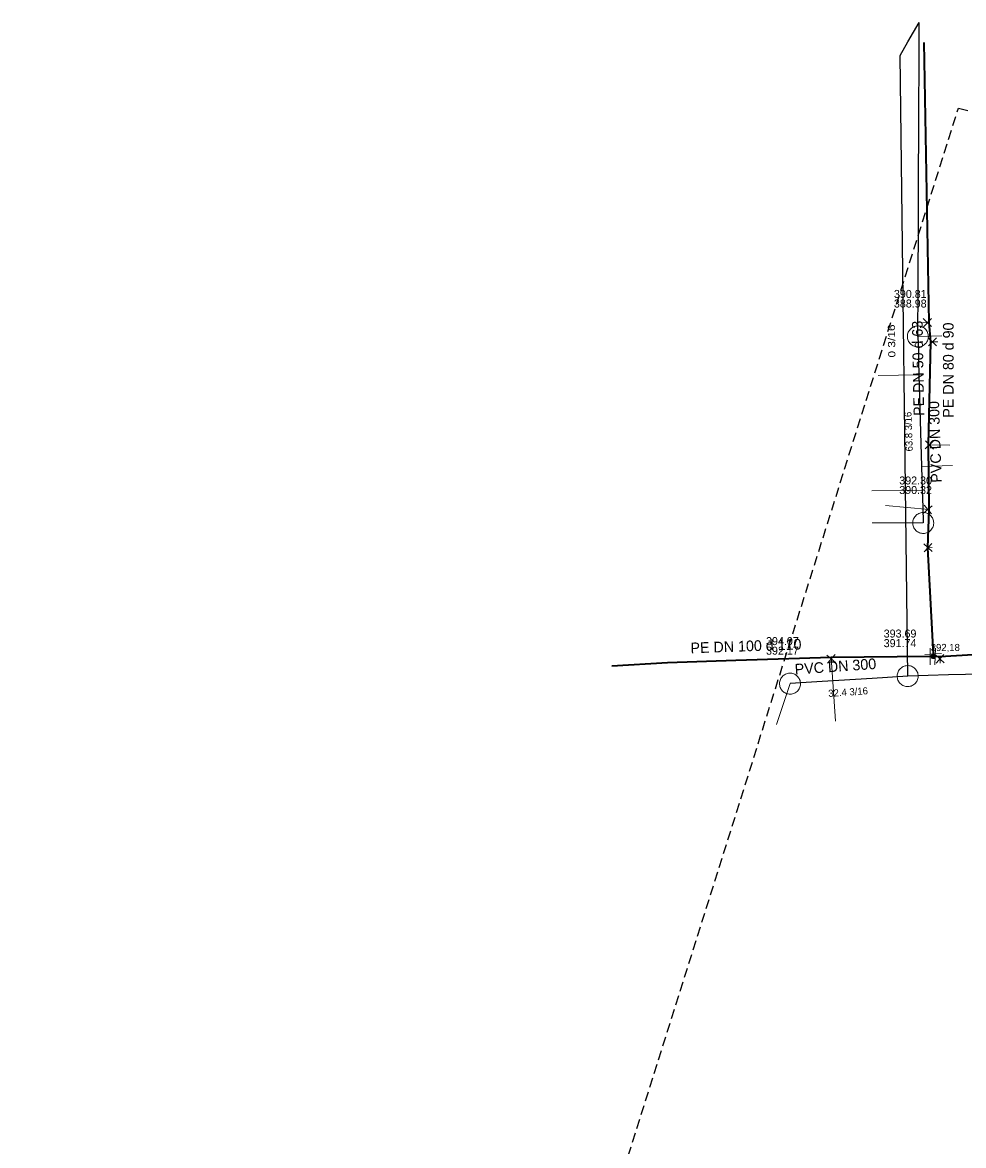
# Model space of a CAD drawing. Extents: x -772952 to -772403, y -1033777 to -1033210.
# Drawn here: x -772951.7 to -772845.8, y -1033366.6 to -1033240.3 of the extents above; entities that cross this region are included whole.
import ezdxf

# ---------------------------------------------------------------- set-up
doc = ezdxf.new("R2010")
doc.units = 0
doc.header["$LTSCALE"] = 0.36
doc.linetypes.add('MEDIUM_DASHED', pattern=[4.5, 3, -1.5])
for name, color, linetype, lineweight in [('15', 7, 'Continuous', 13), ('16', 7, 'Continuous', 35), ('2', 7, 'Continuous', 25), ('20', 7, 'Continuous', 13), ('4', 7, 'Continuous', 13), ('57', 7, 'Continuous', 13), ('59', 7, 'Continuous', 13), ('62', 7, 'MEDIUM_DASHED', 25)]:
    doc.layers.add(name, color=color, linetype=linetype, lineweight=lineweight)
for name, color, linetype in [('17', 7, 'Continuous'), ('3', 7, 'Continuous'), ('6', 7, 'Continuous')]:
    doc.layers.add(name, color=color, linetype=linetype)

msp = doc.modelspace()

# ---------------------------------------------------------------- linework, layer by layer
at = {"layer": '15'}
for p, q in [((-772850.349, -1033273.617), (-772849.404, -1033274.512)), ((-772849.434, -1033273.596), (-772850.323, -1033274.532)), ((-772848.839, -1033276.682), (-772849.78, -1033275.783)), ((-772849.754, -1033276.699), (-772848.86, -1033275.767)), ((-772850.115, -1033288.268), (-772849.181, -1033287.376)), ((-772849.2, -1033288.291), (-772850.101, -1033287.352)), ((-772849.326, -1033294.682), (-772850.32, -1033295.506)), ((-772850.237, -1033294.594), (-772849.404, -1033295.595)), ((-772849.334, -1033299.819), (-772850.298, -1033298.944)), ((-772850.248, -1033299.859), (-772849.378, -1033298.905)), ((-772849.568, -1033312.563), (-772849.585, -1033310.701)), ((-772849.045, -1033312.567), (-772848.97, -1033310.707)), ((-772861.183, -1033311.468), (-772860.213, -1033312.318)), ((-772861.126, -1033312.381), (-772860.27, -1033311.4)), ((-772848.304, -1033311.3), (-772850.164, -1033311.399)), ((-772848.932, -1033311.463), (-772847.984, -1033312.339)), ((-772848.898, -1033312.377), (-772848.017, -1033311.419))]:
    msp.add_line(p, q, dxfattribs=at)
for points in [[(-772849.449, -1033311.619), (-772849.445, -1033311.671), (-772849.43, -1033311.722), (-772849.403, -1033311.767), (-772849.368, -1033311.805), (-772849.324, -1033311.834), (-772849.275, -1033311.853), (-772849.222, -1033311.859), (-772849.169, -1033311.854), (-772849.12, -1033311.837), (-772849.076, -1033311.81), (-772849.038, -1033311.772), (-772849.01, -1033311.728), (-772848.992, -1033311.678), (-772848.987, -1033311.626), (-772848.993, -1033311.574), (-772849.011, -1033311.524), (-772849.04, -1033311.48), (-772849.078, -1033311.444), (-772849.123, -1033311.417), (-772849.173, -1033311.401), (-772849.226, -1033311.397), (-772849.278, -1033311.404), (-772849.326, -1033311.424), (-772849.371, -1033311.453), (-772849.406, -1033311.492), (-772849.432, -1033311.537), (-772849.446, -1033311.588)], [(-772849.419, -1033311.62), (-772849.415, -1033311.669), (-772849.4, -1033311.716), (-772849.374, -1033311.757), (-772849.338, -1033311.79), (-772849.295, -1033311.814), (-772849.247, -1033311.827), (-772849.198, -1033311.829), (-772849.151, -1033311.818), (-772849.107, -1033311.796), (-772849.07, -1033311.764), (-772849.041, -1033311.724), (-772849.023, -1033311.678), (-772849.017, -1033311.629), (-772849.022, -1033311.581), (-772849.04, -1033311.535), (-772849.068, -1033311.494), (-772849.105, -1033311.461), (-772849.148, -1033311.44), (-772849.195, -1033311.428), (-772849.244, -1033311.428), (-772849.292, -1033311.441), (-772849.336, -1033311.464), (-772849.371, -1033311.497), (-772849.399, -1033311.538), (-772849.415, -1033311.584)], [(-772849.389, -1033311.621), (-772849.385, -1033311.666), (-772849.37, -1033311.709), (-772849.343, -1033311.745), (-772849.308, -1033311.774), (-772849.267, -1033311.792), (-772849.222, -1033311.799), (-772849.177, -1033311.795), (-772849.135, -1033311.777), (-772849.099, -1033311.751), (-772849.071, -1033311.715), (-772849.053, -1033311.674), (-772849.047, -1033311.629), (-772849.053, -1033311.584), (-772849.07, -1033311.542), (-772849.098, -1033311.507), (-772849.133, -1033311.479), (-772849.176, -1033311.462), (-772849.221, -1033311.457), (-772849.266, -1033311.463), (-772849.307, -1033311.481), (-772849.342, -1033311.509), (-772849.369, -1033311.546), (-772849.385, -1033311.588)], [(-772849.359, -1033311.622), (-772849.356, -1033311.664), (-772849.34, -1033311.701), (-772849.314, -1033311.733), (-772849.28, -1033311.756), (-772849.24, -1033311.768), (-772849.199, -1033311.768), (-772849.16, -1033311.756), (-772849.125, -1033311.734), (-772849.098, -1033311.703), (-772849.082, -1033311.665), (-772849.077, -1033311.625), (-772849.084, -1033311.584), (-772849.102, -1033311.548), (-772849.13, -1033311.517), (-772849.166, -1033311.497), (-772849.206, -1033311.487), (-772849.247, -1033311.49), (-772849.286, -1033311.503), (-772849.319, -1033311.528), (-772849.343, -1033311.561), (-772849.357, -1033311.599)], [(-772849.329, -1033311.624), (-772849.326, -1033311.66), (-772849.309, -1033311.692), (-772849.284, -1033311.718), (-772849.251, -1033311.735), (-772849.215, -1033311.739), (-772849.18, -1033311.733), (-772849.148, -1033311.714), (-772849.124, -1033311.687), (-772849.109, -1033311.653), (-772849.108, -1033311.616), (-772849.118, -1033311.581), (-772849.137, -1033311.551), (-772849.166, -1033311.529), (-772849.201, -1033311.518), (-772849.238, -1033311.518), (-772849.273, -1033311.531), (-772849.301, -1033311.553), (-772849.321, -1033311.584), (-772849.329, -1033311.619)], [(-772849.299, -1033311.625), (-772849.296, -1033311.656), (-772849.28, -1033311.683), (-772849.254, -1033311.701), (-772849.225, -1033311.709), (-772849.194, -1033311.706), (-772849.166, -1033311.69), (-772849.147, -1033311.667), (-772849.138, -1033311.636), (-772849.141, -1033311.606), (-772849.154, -1033311.578), (-772849.178, -1033311.558), (-772849.207, -1033311.547), (-772849.238, -1033311.549), (-772849.267, -1033311.562), (-772849.288, -1033311.585), (-772849.299, -1033311.614)], [(-772849.269, -1033311.626), (-772849.265, -1033311.65), (-772849.249, -1033311.669), (-772849.227, -1033311.679), (-772849.202, -1033311.677), (-772849.181, -1033311.664), (-772849.169, -1033311.642), (-772849.168, -1033311.617), (-772849.179, -1033311.596), (-772849.199, -1033311.581), (-772849.223, -1033311.577), (-772849.247, -1033311.585), (-772849.263, -1033311.602)], [(-772849.239, -1033311.627), (-772849.235, -1033311.642), (-772849.22, -1033311.649), (-772849.205, -1033311.646), (-772849.198, -1033311.632), (-772849.201, -1033311.617), (-772849.214, -1033311.607), (-772849.229, -1033311.61), (-772849.239, -1033311.621)]]:
    msp.add_lwpolyline(points, close=True, dxfattribs=at)
at = {"layer": '16'}
for p, q in [((-772849.219, -1033311.629), (-772849.577, -1033311.633)), ((-772849.234, -1033311.35), (-772849.219, -1033311.629)), ((-772849.008, -1033311.638), (-772849.219, -1033311.629))]:
    msp.add_line(p, q, dxfattribs=at)
for points in [[(-772850.285, -1033242.579), (-772849.71, -1033274.059), (-772849.539, -1033276.239), (-772849.809, -1033287.82), (-772849.728, -1033295.103), (-772849.87, -1033299.386), (-772849.234, -1033311.35)], [(-772849.577, -1033311.633), (-772860.71, -1033311.739), (-772871.449, -1033312.079), (-772879.129, -1033312.329), (-772885.375, -1033312.733)], [(-772816.318, -1033310.962), (-772833.089, -1033311.01), (-772839.089, -1033311.109), (-772848.469, -1033311.66), (-772849.008, -1033311.638)]]:
    msp.add_lwpolyline(points, dxfattribs=at)
at = {"layer": '2'}
for points in [[(-772852.1, -1033313.83), (-772852.95, -1033244.02), (-772852.064, -1033242.492), (-772850.8, -1033240.31)], [(-772850.95, -1033275.63), (-772850.943, -1033274.104), (-772850.933, -1033271.703), (-772850.834, -1033249.545), (-772850.821, -1033245.481), (-772850.81, -1033242.895), (-772850.8, -1033240.31)], [(-772850.95, -1033275.63), (-772850.9, -1033277.374), (-772850.87, -1033278.415), (-772850.826, -1033279.937), (-772850.531, -1033290.261), (-772850.478, -1033292.935), (-772850.401, -1033294.818), (-772850.35, -1033296.61)], [(-772826.73, -1033313.16), (-772830.297, -1033313.254), (-772832.988, -1033313.325), (-772838.783, -1033313.478), (-772843.679, -1033313.607), (-772847.513, -1033313.708), (-772852.1, -1033313.83)], [(-772852.1, -1033313.83), (-772856.089, -1033314.086), (-772861.706, -1033314.446), (-772865.34, -1033314.68)]]:
    msp.add_lwpolyline(points, dxfattribs=at)
at = {"layer": '4'}
for points in [[(-772849.769, -1033275.63), (-772849.776, -1033275.511), (-772849.794, -1033275.394), (-772849.823, -1033275.278), (-772849.864, -1033275.167), (-772849.916, -1033275.06), (-772849.978, -1033274.959), (-772850.051, -1033274.864), (-772850.132, -1033274.778), (-772850.223, -1033274.7), (-772850.321, -1033274.631), (-772850.424, -1033274.573), (-772850.532, -1033274.526), (-772850.647, -1033274.489), (-772850.762, -1033274.464), (-772850.88, -1033274.452), (-772851, -1033274.451), (-772851.119, -1033274.462), (-772851.235, -1033274.485), (-772851.348, -1033274.519), (-772851.458, -1033274.565), (-772851.563, -1033274.622), (-772851.662, -1033274.689), (-772851.752, -1033274.765), (-772851.836, -1033274.85), (-772851.909, -1033274.944), (-772851.973, -1033275.044), (-772852.027, -1033275.15), (-772852.071, -1033275.261), (-772852.103, -1033275.375), (-772852.122, -1033275.493), (-772852.13, -1033275.612), (-772852.125, -1033275.73), (-772852.11, -1033275.848), (-772852.081, -1033275.964), (-772852.043, -1033276.076), (-772851.992, -1033276.184), (-772851.931, -1033276.286), (-772851.86, -1033276.382), (-772851.779, -1033276.469), (-772851.691, -1033276.549), (-772851.595, -1033276.619), (-772851.492, -1033276.679), (-772851.384, -1033276.728), (-772851.271, -1033276.766), (-772851.154, -1033276.792), (-772851.037, -1033276.807), (-772850.918, -1033276.81), (-772850.799, -1033276.801), (-772850.681, -1033276.78), (-772850.568, -1033276.747), (-772850.458, -1033276.703), (-772850.352, -1033276.648), (-772850.252, -1033276.582), (-772850.159, -1033276.507), (-772850.076, -1033276.423), (-772850, -1033276.331), (-772849.934, -1033276.232), (-772849.879, -1033276.127), (-772849.835, -1033276.017), (-772849.801, -1033275.903), (-772849.779, -1033275.786), (-772849.769, -1033275.667)], [(-772849.169, -1033296.609), (-772849.176, -1033296.49), (-772849.194, -1033296.373), (-772849.223, -1033296.257), (-772849.264, -1033296.146), (-772849.316, -1033296.039), (-772849.379, -1033295.938), (-772849.451, -1033295.843), (-772849.532, -1033295.757), (-772849.623, -1033295.679), (-772849.721, -1033295.61), (-772849.824, -1033295.552), (-772849.933, -1033295.505), (-772850.047, -1033295.468), (-772850.163, -1033295.443), (-772850.281, -1033295.431), (-772850.4, -1033295.43), (-772850.519, -1033295.441), (-772850.635, -1033295.464), (-772850.749, -1033295.498), (-772850.858, -1033295.544), (-772850.963, -1033295.601), (-772851.062, -1033295.668), (-772851.152, -1033295.744), (-772851.236, -1033295.829), (-772851.309, -1033295.923), (-772851.374, -1033296.023), (-772851.428, -1033296.129), (-772851.471, -1033296.24), (-772851.503, -1033296.354), (-772851.522, -1033296.472), (-772851.53, -1033296.591), (-772851.526, -1033296.709), (-772851.51, -1033296.827), (-772851.482, -1033296.943), (-772851.443, -1033297.055), (-772851.392, -1033297.163), (-772851.331, -1033297.265), (-772851.26, -1033297.361), (-772851.179, -1033297.448), (-772851.091, -1033297.528), (-772850.995, -1033297.598), (-772850.892, -1033297.658), (-772850.784, -1033297.707), (-772850.671, -1033297.745), (-772850.554, -1033297.771), (-772850.437, -1033297.786), (-772850.318, -1033297.789), (-772850.2, -1033297.78), (-772850.081, -1033297.759), (-772849.968, -1033297.726), (-772849.858, -1033297.682), (-772849.752, -1033297.627), (-772849.652, -1033297.561), (-772849.559, -1033297.486), (-772849.476, -1033297.402), (-772849.401, -1033297.31), (-772849.335, -1033297.211), (-772849.279, -1033297.106), (-772849.235, -1033296.996), (-772849.201, -1033296.882), (-772849.179, -1033296.765), (-772849.169, -1033296.646)], [(-772850.919, -1033313.83), (-772850.926, -1033313.711), (-772850.944, -1033313.594), (-772850.973, -1033313.478), (-772851.014, -1033313.367), (-772851.066, -1033313.26), (-772851.129, -1033313.159), (-772851.201, -1033313.064), (-772851.282, -1033312.978), (-772851.373, -1033312.9), (-772851.471, -1033312.831), (-772851.574, -1033312.773), (-772851.683, -1033312.726), (-772851.797, -1033312.689), (-772851.913, -1033312.664), (-772852.031, -1033312.652), (-772852.15, -1033312.651), (-772852.269, -1033312.662), (-772852.385, -1033312.685), (-772852.499, -1033312.719), (-772852.608, -1033312.765), (-772852.713, -1033312.822), (-772852.812, -1033312.889), (-772852.902, -1033312.965), (-772852.986, -1033313.05), (-772853.059, -1033313.144), (-772853.124, -1033313.244), (-772853.178, -1033313.35), (-772853.221, -1033313.461), (-772853.253, -1033313.575), (-772853.272, -1033313.693), (-772853.28, -1033313.812), (-772853.276, -1033313.93), (-772853.26, -1033314.048), (-772853.232, -1033314.164), (-772853.193, -1033314.276), (-772853.142, -1033314.384), (-772853.081, -1033314.486), (-772853.01, -1033314.582), (-772852.929, -1033314.669), (-772852.841, -1033314.749), (-772852.745, -1033314.819), (-772852.642, -1033314.879), (-772852.534, -1033314.928), (-772852.421, -1033314.966), (-772852.304, -1033314.992), (-772852.187, -1033315.007), (-772852.068, -1033315.01), (-772851.95, -1033315.001), (-772851.831, -1033314.98), (-772851.718, -1033314.947), (-772851.608, -1033314.903), (-772851.502, -1033314.848), (-772851.402, -1033314.782), (-772851.309, -1033314.707), (-772851.226, -1033314.623), (-772851.151, -1033314.531), (-772851.085, -1033314.432), (-772851.029, -1033314.327), (-772850.985, -1033314.217), (-772850.951, -1033314.103), (-772850.929, -1033313.986), (-772850.919, -1033313.867)], [(-772864.159, -1033314.68), (-772864.166, -1033314.561), (-772864.184, -1033314.444), (-772864.213, -1033314.328), (-772864.254, -1033314.217), (-772864.306, -1033314.11), (-772864.369, -1033314.009), (-772864.441, -1033313.914), (-772864.522, -1033313.828), (-772864.613, -1033313.75), (-772864.711, -1033313.681), (-772864.814, -1033313.623), (-772864.923, -1033313.576), (-772865.037, -1033313.539), (-772865.152, -1033313.514), (-772865.271, -1033313.502), (-772865.39, -1033313.501), (-772865.509, -1033313.512), (-772865.625, -1033313.535), (-772865.739, -1033313.569), (-772865.848, -1033313.615), (-772865.953, -1033313.672), (-772866.052, -1033313.739), (-772866.142, -1033313.815), (-772866.226, -1033313.9), (-772866.299, -1033313.994), (-772866.364, -1033314.094), (-772866.418, -1033314.2), (-772866.461, -1033314.311), (-772866.493, -1033314.425), (-772866.512, -1033314.543), (-772866.52, -1033314.662), (-772866.516, -1033314.78), (-772866.5, -1033314.898), (-772866.472, -1033315.014), (-772866.433, -1033315.126), (-772866.382, -1033315.234), (-772866.321, -1033315.336), (-772866.25, -1033315.432), (-772866.169, -1033315.519), (-772866.081, -1033315.599), (-772865.985, -1033315.669), (-772865.882, -1033315.729), (-772865.774, -1033315.778), (-772865.661, -1033315.816), (-772865.544, -1033315.842), (-772865.427, -1033315.857), (-772865.308, -1033315.86), (-772865.19, -1033315.851), (-772865.071, -1033315.83), (-772864.958, -1033315.797), (-772864.848, -1033315.753), (-772864.742, -1033315.698), (-772864.642, -1033315.632), (-772864.549, -1033315.557), (-772864.466, -1033315.473), (-772864.391, -1033315.381), (-772864.325, -1033315.282), (-772864.269, -1033315.177), (-772864.225, -1033315.067), (-772864.191, -1033314.953), (-772864.169, -1033314.836), (-772864.159, -1033314.717)]]:
    msp.add_lwpolyline(points, close=True, dxfattribs=at)
at = {"layer": '57'}
for p, q in [((-772850.95, -1033275.63), (-772848.25, -1033275.55)), ((-772850.826, -1033279.937), (-772855.41, -1033280.01)), ((-772850.531, -1033290.261), (-772847.05, -1033290.15)), ((-772850.478, -1033292.935), (-772856.14, -1033292.99)), ((-772850.35, -1033296.61), (-772856.1, -1033296.6)), ((-772865.34, -1033314.68), (-772866.851, -1033319.28))]:
    msp.add_line(p, q, dxfattribs=at)
at = {"layer": '59'}
for p, q in [((-772849.71, -1033274.059), (-772850.42, -1033274.079)), ((-772849.539, -1033276.239), (-772848.699, -1033276.219)), ((-772849.809, -1033287.82), (-772847.339, -1033287.87)), ((-772849.728, -1033295.103), (-772854.6, -1033294.66)), ((-772849.87, -1033299.386), (-772849.339, -1033299.359)), ((-772860.71, -1033311.739), (-772860.219, -1033318.89)), ((-772848.469, -1033311.66), (-772848.44, -1033312.37))]:
    msp.add_line(p, q, dxfattribs=at)
at = {"layer": '62'}
msp.add_lwpolyline([(-772641.514, -1033776.98), (-772641.529, -1033776.987), (-772951.708, -1033584.106), (-772846.395, -1033249.938), (-772562.451, -1033323.146)], close=True, dxfattribs=at)

# ---------------------------------------------------------------- texts
at = {"layer": '17'}
for s, rotation, p in [('PE DN 80 d 90 ', 90, (-772846.929, -1033284.765)), ('PE DN 100 d 110 ', 2, (-772876.515, -1033311.268))]:
    msp.add_text(s, height=1.2, rotation=rotation, dxfattribs=at).set_placement(p)
at = {"layer": '20'}
msp.add_text('392,18', height=0.8, dxfattribs=at).set_placement((-772849.502, -1033311.011))
at = {"layer": '3'}
for s, height, rotation, p in [('PE DN 50 d 63 ', 1.2, 91, (-772850.236, -1033284.554)), ('PVC DN 300', 1.2, 92, (-772848.26, -1033292.054)), ('63.8 3/16', 0.8, 92, (-772851.524, -1033288.544)), ('PVC DN 300', 1.2, 4, (-772864.77, -1033313.667)), ('32.4 3/16', 0.8, 4, (-772861, -1033316.18))]:
    msp.add_text(s, height=height, rotation=rotation, dxfattribs=at).set_placement(p)
at = {"layer": '3', "width": 1.25}
msp.add_text('0 3/16 ', height=0.8, rotation=91, dxfattribs=at).set_placement((-772853.479, -1033277.991))
at = {"layer": '6'}
for s, p in [('390.81', (-772853.648, -1033271.297)), ('388.98', (-772853.648, -1033272.374)), ('392.30', (-772853.048, -1033292.277)), ('390.32', (-772853.048, -1033293.354)), ('394.07', (-772868.038, -1033310.347)), ('393.69', (-772854.798, -1033309.497)), ('392.17', (-772868.038, -1033311.424)), ('391.74', (-772854.798, -1033310.574))]:
    msp.add_text(s, height=0.9, dxfattribs=at).set_placement(p)

doc.saveas('drawing.dxf')
